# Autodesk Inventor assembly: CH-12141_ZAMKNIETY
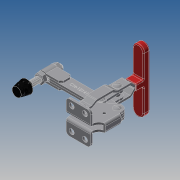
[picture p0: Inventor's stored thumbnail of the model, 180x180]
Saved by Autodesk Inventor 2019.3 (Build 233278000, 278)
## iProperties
Company: Microsoft
Created: 2017-11
Part Number: CH-12141_ZAMKNIETY
Material: Ogólny
Description: STEP AP203
Document SubType Name: Assembly
Designer: Admin
Sending System: SolidWorks 2015
Preprocessor: SwSTEP 2.0
Title: CH-12141.STEP
Author: Windows
Revision Number: ÈÎºÎ
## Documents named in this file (10)
- E:\SERWER_ZAPAS\MODELE brakujace\brakujące stepy_08012019\CH-12141\CH-12141_ZAMKNIETY.iam
- E:\SERWER_ZAPAS\MODELE brakujace\brakujące stepy_08012019\CH-12141\CH-12130-01 FLANGED BASE.ipt
- E:\SERWER_ZAPAS\MODELE brakujace\brakujące stepy_08012019\CH-12141\CH-12130-04 CONNECTING-PLATE.ipt
- E:\SERWER_ZAPAS\MODELE brakujace\brakujące stepy_08012019\CH-12141\CH-12130-05.ipt
- E:\SERWER_ZAPAS\MODELE brakujace\brakujące stepy_08012019\CH-12141\CH-12130-08.ipt
- E:\SERWER_ZAPAS\MODELE brakujace\brakujące stepy_08012019\CH-12141\CH-12130-06.ipt
- E:\SERWER_ZAPAS\MODELE brakujace\brakujące stepy_08012019\CH-12141\CH-FC-56212 Nut.ipt
- E:\SERWER_ZAPAS\MODELE brakujace\brakujące stepy_08012019\CH-12141\CH-FC-56212 SPINDLE SUPPLIED.ipt
- E:\SERWER_ZAPAS\MODELE brakujace\brakujące stepy_08012019\CH-12141\CH-12141-02 SHORT SOLID BAR_Ä¬ÈÏ_°´¼Ó¹¤_.ipt
- E:\SERWER_ZAPAS\MODELE brakujace\brakujące stepy_08012019\CH-12141\CH-12148-03 T-HANDLE.ipt
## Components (12 placed, 12 different names)
1. CH-12130-01 FLANGED BASE_1
2. CH-12130-04 CONNECTING-PLATE_2
3. CH-12130-05_3
4. CH-12130-08_4
5. CH-12130-06_5
6. CH-12130-06_6
7. CH-12130-08_7
8. CH-FC-56212 Nut_8
9. CH-FC-56212 SPINDLE SUPPLIED_9
10. CH-FC-56212 Nut_10
11. CH-12141-02 SHORT SOLID BAR_Ä¬ÈÏ<°´¼Ó¹¤>_11
12. CH-12148-03 T-HANDLE_12
